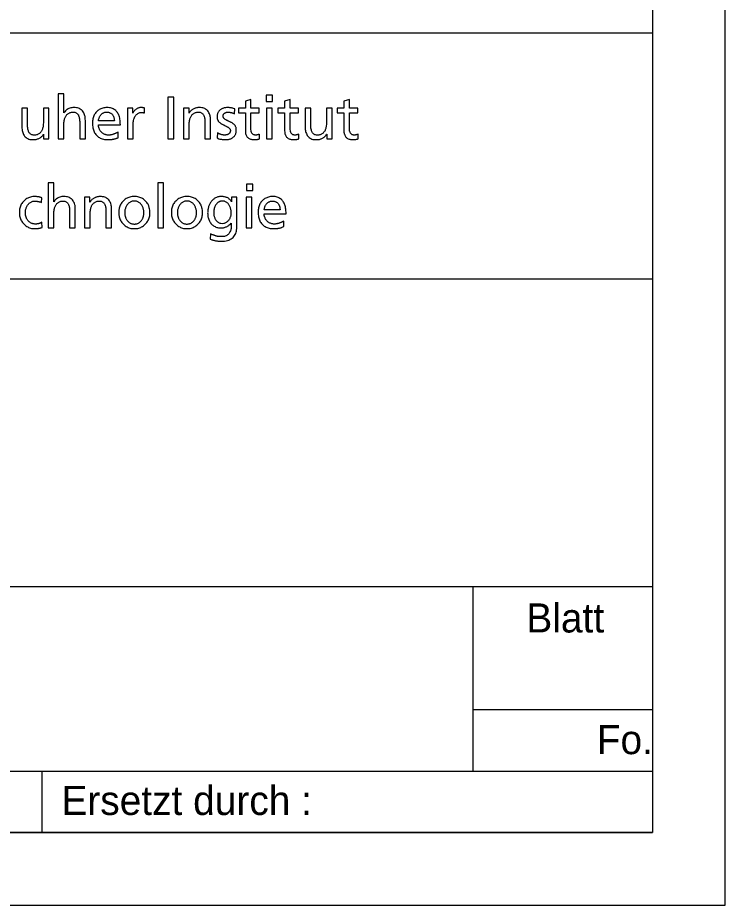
# Model space of a CAD drawing. Extents: x 0 to 148, y 0 to 105.
# Drawn here: x 136.33 to 148.5, y 0 to 15.26 of the extents above; entities that cross this region are included whole.
import ezdxf

# ---------------------------------------------------------------- set-up
doc = ezdxf.new("R2010")
doc.units = 0
doc.layers.add('90_Plankopf', color=7, linetype='Continuous')

msp = doc.modelspace()

# ---------------------------------------------------------------- linework, layer by layer
at = {"layer": '90_Plankopf'}
for p, q in [((147.25, 21.248), (147.25, 1.25)), ((102.78, 14.998), (147.25, 14.998)), ((102.78, 14.998), (147.25, 14.998)), ((147.25, 14.998), (147.25, 1.25)), ((138.514, 13.621), (138.514, 13.708)), ((140.058, 13.61), (140.066, 13.694)), ((137.993, 13.49), (137.721, 13.49)), ((137.721, 13.418), (138.096, 13.418)), ((138.056, 13.198), (138.056, 13.295)), ((139.768, 13.28), (139.763, 13.193)), ((140.49, 13.179), (140.49, 13.261)), ((141.166, 13.179), (141.166, 13.261)), ((142.186, 13.179), (142.186, 13.261)), ((136.738, 12.084), (136.746, 12.165)), ((140.843, 11.96), (140.571, 11.96)), ((140.571, 11.888), (140.946, 11.888)), ((140.906, 11.668), (140.906, 11.765)), ((136.75, 11.656), (136.743, 11.743)), ((139.649, 11.543), (139.639, 11.454)), ((126.25, 10.768), (147.25, 10.768)), ((126.25, 5.48), (147.25, 5.48)), ((144.162, 2.308), (144.162, 5.48)), ((144.162, 3.365), (147.25, 3.365)), ((126.25, 2.308), (147.25, 2.308)), ((136.75, 1.25), (136.75, 2.308)), ((147.25, 1.25), (102.78, 1.25)), ((105.7, 1.25), (147.25, 1.25)), ((105.7, 1.25), (147.25, 1.25))]:
    msp.add_line(p, q, dxfattribs=at)
for points in [[(0, 0), (148.5, 0), (148.5, 105), (0, 105)], [(6.25, 103.75), (147.25, 103.75), (147.25, 1.25), (6.25, 1.25)]]:
    msp.add_lwpolyline(points, close=True, dxfattribs=at)
for points in [[(137.127, 13.627), (137.125, 13.627), (137.125, 13.95), (137.028, 13.95), (137.028, 13.176), (137.125, 13.176), (137.125, 13.42)], [(138.912, 13.176), (139.015, 13.176), (139.015, 13.897), (138.912, 13.897), (138.912, 13.176)], [(140.713, 13.82), (140.713, 13.93), (140.604, 13.93), (140.604, 13.82), (140.713, 13.82)], [(140.343, 13.336), (140.343, 13.624), (140.482, 13.624), (140.482, 13.703), (140.343, 13.703), (140.343, 13.855), (140.246, 13.824), (140.246, 13.703), (140.127, 13.703), (140.127, 13.624), (140.246, 13.624), (140.246, 13.317)], [(141.019, 13.336), (141.019, 13.624), (141.158, 13.624), (141.158, 13.703), (141.019, 13.703), (141.019, 13.855), (140.922, 13.824), (140.922, 13.703), (140.803, 13.703), (140.803, 13.624), (140.922, 13.624), (140.922, 13.317)], [(142.038, 13.336), (142.038, 13.624), (142.178, 13.624), (142.178, 13.703), (142.038, 13.703), (142.038, 13.855), (141.941, 13.824), (141.941, 13.703), (141.823, 13.703), (141.823, 13.624), (141.941, 13.624), (141.941, 13.317)], [(136.501, 13.43), (136.501, 13.703), (136.404, 13.703), (136.404, 13.39)], [(136.773, 13.26), (136.775, 13.26), (136.775, 13.176), (136.869, 13.176), (136.869, 13.703), (136.772, 13.703), (136.772, 13.459)], [(138.313, 13.621), (138.311, 13.621), (138.311, 13.703), (138.22, 13.703), (138.22, 13.176), (138.317, 13.176), (138.317, 13.416)], [(139.279, 13.619), (139.277, 13.619), (139.277, 13.703), (139.183, 13.703), (139.183, 13.176), (139.28, 13.176), (139.28, 13.42)], [(140.61, 13.703), (140.61, 13.176), (140.707, 13.176), (140.707, 13.703), (140.61, 13.703)], [(141.371, 13.43), (141.371, 13.703), (141.274, 13.703), (141.274, 13.39)], [(141.643, 13.26), (141.645, 13.26), (141.645, 13.176), (141.739, 13.176), (141.739, 13.703), (141.642, 13.703), (141.642, 13.459)], [(137.397, 13.449), (137.397, 13.176), (137.494, 13.176), (137.494, 13.489)], [(139.551, 13.449), (139.551, 13.176), (139.648, 13.176), (139.648, 13.489)], [(136.955, 12.097), (136.953, 12.097), (136.953, 12.42), (136.856, 12.42), (136.856, 11.647), (136.953, 11.647), (136.953, 11.89)], [(138.741, 11.647), (138.838, 11.647), (138.838, 12.42), (138.741, 12.42), (138.741, 11.647)], [(140.373, 12.29), (140.373, 12.4), (140.264, 12.4), (140.264, 12.29), (140.373, 12.29)], [(137.576, 12.089), (137.574, 12.089), (137.574, 12.173), (137.48, 12.173), (137.48, 11.647), (137.577, 11.647), (137.577, 11.89)], [(140.099, 11.669), (140.099, 12.173), (140.009, 12.173), (140.009, 12.094), (140.007, 12.094)], [(140.258, 12.173), (140.258, 11.647), (140.355, 11.647), (140.355, 12.173), (140.258, 12.173)], [(137.224, 11.919), (137.224, 11.647), (137.321, 11.647), (137.321, 11.959)], [(137.848, 11.919), (137.848, 11.647), (137.945, 11.647), (137.945, 11.959)], [(140, 11.728), (140.002, 11.728), (140.002, 11.677)]]:
    msp.add_lwpolyline(points, dxfattribs=at)
for points in [[(137.125, 13.42), (137.125, 13.452), (137.128, 13.481), (137.135, 13.508), (137.141, 13.534), (137.151, 13.557), (137.164, 13.576), (137.177, 13.595), (137.194, 13.61), (137.214, 13.621), (137.234, 13.631), (137.258, 13.636), (137.285, 13.637), (137.313, 13.635), (137.335, 13.627), (137.352, 13.613), (137.368, 13.599), (137.38, 13.578), (137.387, 13.551), (137.394, 13.524), (137.397, 13.49), (137.397, 13.449)], [(137.494, 13.489), (137.494, 13.536), (137.487, 13.577), (137.473, 13.61), (137.459, 13.644), (137.437, 13.67), (137.408, 13.688), (137.379, 13.706), (137.342, 13.715), (137.297, 13.715), (137.26, 13.715), (137.227, 13.707), (137.198, 13.692), (137.169, 13.677), (137.145, 13.655), (137.127, 13.627)], [(138.096, 13.418), (138.096, 13.46), (138.092, 13.5), (138.085, 13.536), (138.077, 13.572), (138.064, 13.603), (138.046, 13.63), (138.028, 13.657), (138.004, 13.677), (137.974, 13.692), (137.945, 13.707), (137.908, 13.715), (137.864, 13.715), (137.827, 13.715), (137.793, 13.708), (137.763, 13.695), (137.733, 13.682), (137.707, 13.664), (137.685, 13.64), (137.664, 13.617), (137.647, 13.589), (137.635, 13.556), (137.624, 13.524), (137.618, 13.488), (137.618, 13.449), (137.618, 13.406), (137.623, 13.367), (137.634, 13.332), (137.645, 13.297), (137.661, 13.267), (137.684, 13.242), (137.706, 13.217), (137.734, 13.198), (137.769, 13.184), (137.803, 13.171), (137.843, 13.164), (137.89, 13.164), (137.919, 13.164), (137.943, 13.166), (137.963, 13.17), (137.983, 13.174), (138.001, 13.178), (138.016, 13.183), (138.03, 13.188), (138.044, 13.193), (138.056, 13.198)], [(137.721, 13.49), (137.722, 13.507), (137.726, 13.524), (137.733, 13.542), (137.739, 13.559), (137.747, 13.574), (137.759, 13.589), (137.77, 13.603), (137.784, 13.615), (137.801, 13.623), (137.818, 13.632), (137.838, 13.636), (137.862, 13.637), (137.883, 13.636), (137.902, 13.633), (137.918, 13.625), (137.934, 13.617), (137.948, 13.607), (137.959, 13.594), (137.97, 13.58), (137.979, 13.564), (137.984, 13.547), (137.99, 13.529), (137.993, 13.51), (137.993, 13.49)], [(138.514, 13.708), (138.508, 13.709), (138.501, 13.71), (138.495, 13.712), (138.489, 13.713), (138.482, 13.713), (138.475, 13.714), (138.468, 13.715), (138.46, 13.715), (138.45, 13.715), (138.432, 13.715), (138.413, 13.711), (138.396, 13.703), (138.378, 13.695), (138.362, 13.684), (138.348, 13.67), (138.333, 13.656), (138.322, 13.639), (138.313, 13.621)], [(138.317, 13.416), (138.317, 13.46), (138.323, 13.498), (138.335, 13.53), (138.347, 13.562), (138.363, 13.587), (138.385, 13.604), (138.406, 13.621), (138.432, 13.63), (138.461, 13.63), (138.469, 13.631), (138.478, 13.63), (138.487, 13.629), (138.496, 13.627), (138.505, 13.625), (138.514, 13.621)], [(139.648, 13.489), (139.648, 13.536), (139.641, 13.577), (139.627, 13.61), (139.614, 13.644), (139.592, 13.67), (139.563, 13.688), (139.534, 13.706), (139.497, 13.715), (139.451, 13.715), (139.427, 13.715), (139.403, 13.711), (139.38, 13.704), (139.358, 13.696), (139.338, 13.685), (139.32, 13.67), (139.303, 13.656), (139.289, 13.639), (139.279, 13.619)], [(139.28, 13.42), (139.28, 13.452), (139.283, 13.481), (139.289, 13.508), (139.296, 13.534), (139.305, 13.557), (139.319, 13.576), (139.332, 13.595), (139.348, 13.61), (139.368, 13.621), (139.388, 13.631), (139.412, 13.636), (139.44, 13.637), (139.468, 13.635), (139.49, 13.627), (139.506, 13.613), (139.523, 13.599), (139.534, 13.578), (139.541, 13.551), (139.548, 13.524), (139.551, 13.49), (139.551, 13.449)], [(140.066, 13.694), (140.047, 13.7), (140.028, 13.705), (140.009, 13.709), (139.989, 13.713), (139.968, 13.715), (139.946, 13.715), (139.919, 13.715), (139.895, 13.712), (139.873, 13.705), (139.85, 13.698), (139.831, 13.688), (139.814, 13.675), (139.797, 13.662), (139.784, 13.645), (139.774, 13.625), (139.765, 13.604), (139.76, 13.58), (139.76, 13.553), (139.76, 13.532), (139.764, 13.514), (139.773, 13.498), (139.781, 13.483), (139.791, 13.47), (139.805, 13.459), (139.819, 13.447), (139.833, 13.437), (139.85, 13.429), (139.866, 13.42), (139.882, 13.412), (139.898, 13.404), (139.914, 13.397), (139.929, 13.389), (139.943, 13.38), (139.956, 13.373), (139.967, 13.363), (139.975, 13.353), (139.983, 13.343), (139.988, 13.331), (139.988, 13.318), (139.988, 13.304), (139.985, 13.292), (139.979, 13.282), (139.973, 13.272), (139.965, 13.265), (139.955, 13.259), (139.945, 13.253), (139.935, 13.249), (139.923, 13.246), (139.912, 13.244), (139.9, 13.242), (139.889, 13.242), (139.879, 13.242), (139.867, 13.244), (139.854, 13.247), (139.84, 13.249), (139.825, 13.253), (139.81, 13.259), (139.795, 13.265), (139.781, 13.271), (139.768, 13.28)], [(139.763, 13.193), (139.785, 13.181), (139.809, 13.174), (139.833, 13.17), (139.858, 13.166), (139.882, 13.164), (139.907, 13.164), (139.931, 13.164), (139.954, 13.167), (139.976, 13.174), (139.997, 13.18), (140.017, 13.191), (140.034, 13.204), (140.052, 13.217), (140.065, 13.234), (140.076, 13.255), (140.086, 13.276), (140.091, 13.3), (140.091, 13.328), (140.091, 13.352), (140.087, 13.372), (140.078, 13.389), (140.07, 13.406), (140.059, 13.42), (140.046, 13.431), (140.032, 13.443), (140.017, 13.453), (140.001, 13.461), (139.985, 13.469), (139.969, 13.477), (139.953, 13.484), (139.937, 13.491), (139.922, 13.499), (139.908, 13.507), (139.895, 13.515), (139.884, 13.524), (139.876, 13.534), (139.867, 13.545), (139.863, 13.557), (139.863, 13.573), (139.863, 13.587), (139.868, 13.599), (139.876, 13.609), (139.885, 13.618), (139.896, 13.625), (139.91, 13.63), (139.924, 13.634), (139.939, 13.637), (139.956, 13.637), (139.962, 13.637), (139.969, 13.636), (139.978, 13.634), (139.988, 13.633), (139.997, 13.631), (140.007, 13.628), (140.018, 13.626), (140.027, 13.623), (140.036, 13.62), (140.045, 13.616), (140.052, 13.613), (140.058, 13.61)], [(136.772, 13.459), (136.772, 13.427), (136.769, 13.398), (136.763, 13.371), (136.757, 13.345), (136.747, 13.322), (136.734, 13.303), (136.721, 13.284), (136.704, 13.269), (136.684, 13.258), (136.664, 13.248), (136.64, 13.243), (136.612, 13.242), (136.584, 13.244), (136.562, 13.252), (136.546, 13.266), (136.53, 13.28), (136.518, 13.301), (136.511, 13.328), (136.504, 13.355), (136.501, 13.389), (136.501, 13.43)], [(141.642, 13.459), (141.642, 13.427), (141.639, 13.398), (141.633, 13.371), (141.626, 13.345), (141.617, 13.322), (141.604, 13.303), (141.591, 13.284), (141.574, 13.269), (141.554, 13.258), (141.534, 13.248), (141.51, 13.243), (141.482, 13.242), (141.454, 13.244), (141.432, 13.252), (141.416, 13.266), (141.399, 13.28), (141.388, 13.301), (141.381, 13.328), (141.374, 13.355), (141.371, 13.389), (141.371, 13.43)], [(136.404, 13.39), (136.404, 13.343), (136.411, 13.302), (136.425, 13.269), (136.439, 13.235), (136.46, 13.209), (136.49, 13.191), (136.519, 13.173), (136.556, 13.164), (136.601, 13.164), (136.626, 13.164), (136.649, 13.168), (136.672, 13.176), (136.694, 13.183), (136.715, 13.194), (136.732, 13.209), (136.75, 13.223), (136.764, 13.24), (136.773, 13.26)], [(138.056, 13.295), (138.05, 13.29), (138.041, 13.285), (138.03, 13.279), (138.018, 13.273), (138.005, 13.267), (137.99, 13.261), (137.975, 13.256), (137.96, 13.251), (137.943, 13.248), (137.927, 13.244), (137.91, 13.243), (137.894, 13.242), (137.871, 13.243), (137.849, 13.247), (137.828, 13.255), (137.808, 13.264), (137.789, 13.276), (137.773, 13.291), (137.757, 13.307), (137.744, 13.325), (137.735, 13.347), (137.726, 13.368), (137.721, 13.392), (137.721, 13.418)], [(140.246, 13.317), (140.246, 13.282), (140.253, 13.253), (140.266, 13.23), (140.279, 13.208), (140.297, 13.191), (140.321, 13.18), (140.346, 13.169), (140.374, 13.164), (140.408, 13.164), (140.424, 13.164), (140.438, 13.166), (140.453, 13.169), (140.467, 13.172), (140.479, 13.175), (140.49, 13.179)], [(140.49, 13.261), (140.483, 13.256), (140.474, 13.252), (140.463, 13.248), (140.452, 13.245), (140.439, 13.243), (140.424, 13.242), (140.409, 13.242), (140.396, 13.246), (140.383, 13.253), (140.371, 13.261), (140.361, 13.271), (140.354, 13.285), (140.347, 13.299), (140.343, 13.316), (140.343, 13.336)], [(140.922, 13.317), (140.922, 13.282), (140.929, 13.253), (140.942, 13.23), (140.955, 13.208), (140.973, 13.191), (140.997, 13.18), (141.022, 13.169), (141.05, 13.164), (141.084, 13.164), (141.1, 13.164), (141.114, 13.166), (141.129, 13.169), (141.143, 13.172), (141.155, 13.175), (141.166, 13.179)], [(141.166, 13.261), (141.159, 13.256), (141.15, 13.252), (141.139, 13.248), (141.128, 13.245), (141.115, 13.243), (141.1, 13.242), (141.085, 13.242), (141.072, 13.246), (141.059, 13.253), (141.047, 13.261), (141.037, 13.271), (141.03, 13.285), (141.023, 13.299), (141.019, 13.316), (141.019, 13.336)], [(141.274, 13.39), (141.274, 13.343), (141.281, 13.302), (141.295, 13.269), (141.309, 13.235), (141.33, 13.209), (141.359, 13.191), (141.388, 13.173), (141.426, 13.164), (141.471, 13.164), (141.495, 13.164), (141.519, 13.168), (141.542, 13.176), (141.564, 13.183), (141.584, 13.194), (141.602, 13.209), (141.62, 13.223), (141.633, 13.24), (141.643, 13.26)], [(141.941, 13.317), (141.942, 13.282), (141.948, 13.253), (141.961, 13.23), (141.974, 13.208), (141.993, 13.191), (142.017, 13.18), (142.041, 13.169), (142.07, 13.164), (142.103, 13.164), (142.119, 13.164), (142.134, 13.166), (142.148, 13.169), (142.162, 13.172), (142.175, 13.175), (142.186, 13.179)], [(142.186, 13.261), (142.179, 13.256), (142.17, 13.252), (142.159, 13.248), (142.148, 13.245), (142.135, 13.243), (142.12, 13.242), (142.105, 13.242), (142.091, 13.246), (142.079, 13.253), (142.067, 13.261), (142.057, 13.271), (142.05, 13.285), (142.042, 13.299), (142.039, 13.316), (142.038, 13.336)], [(136.746, 12.165), (136.737, 12.168), (136.725, 12.172), (136.712, 12.175), (136.699, 12.178), (136.685, 12.181), (136.67, 12.182), (136.656, 12.184), (136.642, 12.185), (136.628, 12.185), (136.588, 12.185), (136.551, 12.178), (136.519, 12.165), (136.486, 12.151), (136.458, 12.132), (136.434, 12.107), (136.41, 12.083), (136.392, 12.054), (136.379, 12.02), (136.367, 11.987), (136.36, 11.95), (136.36, 11.91), (136.36, 11.872), (136.367, 11.836), (136.38, 11.803), (136.393, 11.77), (136.411, 11.741), (136.435, 11.716), (136.459, 11.69), (136.487, 11.67), (136.519, 11.656), (136.552, 11.642), (136.589, 11.635), (136.628, 11.634), (136.64, 11.634), (136.653, 11.635), (136.667, 11.636), (136.68, 11.637), (136.694, 11.639), (136.709, 11.642), (136.723, 11.645), (136.737, 11.65), (136.75, 11.656)], [(136.743, 11.743), (136.733, 11.736), (136.722, 11.73), (136.71, 11.726), (136.698, 11.722), (136.686, 11.718), (136.674, 11.716), (136.662, 11.714), (136.65, 11.713), (136.639, 11.713), (136.614, 11.713), (136.592, 11.717), (136.573, 11.724), (136.553, 11.732), (136.537, 11.742), (136.523, 11.755), (136.509, 11.768), (136.498, 11.783), (136.489, 11.8), (136.48, 11.817), (136.474, 11.834), (136.47, 11.853), (136.465, 11.872), (136.463, 11.891), (136.463, 11.91), (136.463, 11.935), (136.467, 11.959), (136.475, 11.983), (136.482, 12.006), (136.493, 12.027), (136.507, 12.046), (136.522, 12.064), (136.539, 12.079), (136.56, 12.09), (136.581, 12.101), (136.605, 12.107), (136.633, 12.107), (136.648, 12.107), (136.665, 12.105), (136.683, 12.101), (136.701, 12.097), (136.719, 12.092), (136.738, 12.084)], [(136.953, 11.89), (136.953, 11.922), (136.956, 11.951), (136.962, 11.978), (136.968, 12.004), (136.978, 12.027), (136.991, 12.046), (137.004, 12.066), (137.021, 12.08), (137.041, 12.091), (137.061, 12.101), (137.085, 12.107), (137.112, 12.107), (137.14, 12.105), (137.163, 12.097), (137.179, 12.083), (137.195, 12.069), (137.207, 12.048), (137.214, 12.021), (137.221, 11.994), (137.224, 11.96), (137.224, 11.919)], [(137.321, 11.959), (137.321, 12.006), (137.314, 12.047), (137.3, 12.081), (137.286, 12.114), (137.264, 12.14), (137.235, 12.158), (137.206, 12.176), (137.169, 12.185), (137.124, 12.185), (137.087, 12.185), (137.054, 12.177), (137.025, 12.162), (136.996, 12.147), (136.972, 12.125), (136.955, 12.097)], [(137.945, 11.959), (137.945, 12.006), (137.938, 12.047), (137.924, 12.081), (137.91, 12.114), (137.889, 12.14), (137.86, 12.158), (137.831, 12.176), (137.793, 12.185), (137.748, 12.185), (137.724, 12.185), (137.7, 12.181), (137.677, 12.174), (137.655, 12.166), (137.635, 12.155), (137.617, 12.141), (137.599, 12.126), (137.586, 12.109), (137.576, 12.089)], [(137.577, 11.89), (137.577, 11.922), (137.58, 11.951), (137.586, 11.978), (137.593, 12.004), (137.602, 12.027), (137.615, 12.046), (137.628, 12.066), (137.645, 12.08), (137.665, 12.091), (137.685, 12.101), (137.709, 12.107), (137.737, 12.107), (137.765, 12.105), (137.787, 12.097), (137.803, 12.083), (137.82, 12.069), (137.831, 12.048), (137.838, 12.021), (137.845, 11.994), (137.848, 11.96), (137.848, 11.919)], [(138.599, 11.973), (138.595, 11.989), (138.591, 12.005), (138.585, 12.02), (138.573, 12.054), (138.555, 12.083), (138.531, 12.107), (138.507, 12.132), (138.479, 12.151), (138.447, 12.165), (138.414, 12.178), (138.377, 12.185), (138.337, 12.185), (138.297, 12.185), (138.26, 12.178), (138.227, 12.165), (138.195, 12.151), (138.166, 12.132), (138.143, 12.107), (138.119, 12.083), (138.101, 12.054), (138.088, 12.02), (138.076, 11.987), (138.069, 11.95), (138.069, 11.91)], [(138.172, 11.91), (138.172, 11.935), (138.176, 11.959), (138.183, 11.983), (138.191, 12.006), (138.202, 12.027), (138.216, 12.046), (138.23, 12.064), (138.247, 12.079), (138.268, 12.09), (138.288, 12.101), (138.311, 12.107), (138.337, 12.107), (138.363, 12.107), (138.386, 12.101), (138.406, 12.09), (138.427, 12.079), (138.444, 12.064), (138.458, 12.046), (138.472, 12.027), (138.483, 12.006), (138.49, 11.983), (138.498, 11.959), (138.501, 11.935), (138.501, 11.91), (138.501, 11.891), (138.499, 11.872), (138.495, 11.853), (138.491, 11.834), (138.485, 11.817), (138.476, 11.8), (138.468, 11.783), (138.457, 11.768), (138.444, 11.755), (138.431, 11.742), (138.416, 11.732), (138.398, 11.724), (138.38, 11.717), (138.36, 11.713), (138.337, 11.713), (138.314, 11.713), (138.294, 11.717), (138.276, 11.724), (138.258, 11.732), (138.243, 11.742), (138.23, 11.755), (138.217, 11.768), (138.206, 11.783), (138.197, 11.8), (138.189, 11.817), (138.183, 11.834), (138.178, 11.853), (138.174, 11.872), (138.172, 11.891), (138.172, 11.91)], [(139.504, 11.973), (139.501, 11.989), (139.496, 12.005), (139.49, 12.02), (139.478, 12.054), (139.46, 12.083), (139.436, 12.107), (139.412, 12.132), (139.384, 12.151), (139.352, 12.165), (139.319, 12.178), (139.282, 12.185), (139.242, 12.185), (139.202, 12.185), (139.165, 12.178), (139.133, 12.165), (139.1, 12.151), (139.072, 12.132), (139.048, 12.107), (139.024, 12.083), (139.006, 12.054), (138.993, 12.02), (138.981, 11.987), (138.974, 11.95), (138.974, 11.91)], [(139.077, 11.91), (139.077, 11.935), (139.081, 11.959), (139.088, 11.983), (139.096, 12.006), (139.107, 12.027), (139.121, 12.046), (139.135, 12.064), (139.152, 12.079), (139.173, 12.09), (139.193, 12.101), (139.216, 12.107), (139.242, 12.107), (139.268, 12.107), (139.291, 12.101), (139.312, 12.09), (139.332, 12.079), (139.349, 12.064), (139.363, 12.046), (139.377, 12.027), (139.388, 12.006), (139.395, 11.983), (139.403, 11.959), (139.406, 11.935), (139.406, 11.91), (139.406, 11.891), (139.404, 11.872), (139.4, 11.853), (139.396, 11.834), (139.39, 11.817), (139.381, 11.8), (139.373, 11.783), (139.362, 11.768), (139.349, 11.755), (139.336, 11.742), (139.321, 11.732), (139.303, 11.724), (139.285, 11.717), (139.265, 11.713), (139.242, 11.713), (139.219, 11.713), (139.199, 11.717), (139.181, 11.724), (139.163, 11.732), (139.148, 11.742), (139.135, 11.755), (139.122, 11.768), (139.111, 11.783), (139.102, 11.8), (139.094, 11.817), (139.088, 11.834), (139.083, 11.853), (139.079, 11.872), (139.077, 11.891), (139.077, 11.91)], [(140.007, 12.094), (139.997, 12.113), (139.985, 12.13), (139.97, 12.143), (139.955, 12.157), (139.936, 12.167), (139.913, 12.174), (139.891, 12.181), (139.864, 12.185), (139.834, 12.185), (139.802, 12.185), (139.773, 12.18), (139.748, 12.169), (139.723, 12.158), (139.701, 12.144), (139.682, 12.126), (139.663, 12.107), (139.648, 12.086), (139.635, 12.062), (139.623, 12.039), (139.614, 12.013), (139.608, 11.987), (139.602, 11.96), (139.598, 11.933), (139.598, 11.906), (139.598, 11.871), (139.603, 11.839), (139.612, 11.808), (139.622, 11.777), (139.636, 11.749), (139.655, 11.725), (139.673, 11.701), (139.696, 11.682), (139.725, 11.668), (139.753, 11.654), (139.786, 11.647), (139.823, 11.647), (139.846, 11.647), (139.868, 11.65), (139.89, 11.656), (139.911, 11.662), (139.932, 11.671), (139.951, 11.683), (139.969, 11.695), (139.986, 11.71), (140, 11.728)], [(139.848, 11.725), (139.825, 11.725), (139.805, 11.73), (139.787, 11.74), (139.769, 11.75), (139.753, 11.764), (139.741, 11.781), (139.728, 11.798), (139.718, 11.818), (139.712, 11.84), (139.705, 11.862), (139.702, 11.886), (139.702, 11.911), (139.702, 11.929), (139.703, 11.947), (139.707, 11.966), (139.711, 11.984), (139.717, 12.002), (139.725, 12.018), (139.733, 12.035), (139.742, 12.05), (139.754, 12.064), (139.766, 12.077), (139.78, 12.087), (139.795, 12.095), (139.811, 12.103), (139.829, 12.107), (139.848, 12.107), (139.874, 12.107), (139.896, 12.101), (139.916, 12.09), (139.935, 12.08), (139.951, 12.065), (139.964, 12.046), (139.976, 12.027), (139.986, 12.006), (139.992, 11.981), (139.999, 11.957), (140.002, 11.931), (140.002, 11.903), (140.002, 11.879), (139.998, 11.856), (139.991, 11.834), (139.983, 11.813), (139.973, 11.794), (139.959, 11.777), (139.945, 11.761), (139.929, 11.748), (139.91, 11.739), (139.892, 11.73), (139.871, 11.725), (139.848, 11.725)], [(140.946, 11.888), (140.946, 11.931), (140.943, 11.97), (140.935, 12.006), (140.927, 12.042), (140.914, 12.073), (140.896, 12.1), (140.878, 12.127), (140.854, 12.148), (140.824, 12.162), (140.795, 12.177), (140.758, 12.185), (140.714, 12.185), (140.677, 12.185), (140.643, 12.178), (140.613, 12.166), (140.583, 12.152), (140.557, 12.134), (140.535, 12.111), (140.514, 12.087), (140.497, 12.059), (140.485, 12.026), (140.474, 11.994), (140.468, 11.958), (140.468, 11.919), (140.468, 11.876), (140.473, 11.837), (140.484, 11.802), (140.495, 11.767), (140.511, 11.737), (140.534, 11.712), (140.556, 11.687), (140.584, 11.668), (140.619, 11.655), (140.653, 11.641), (140.693, 11.634), (140.74, 11.634), (140.769, 11.634), (140.793, 11.636), (140.813, 11.64), (140.834, 11.644), (140.851, 11.648), (140.866, 11.653), (140.88, 11.659), (140.894, 11.664), (140.906, 11.668)], [(140.571, 11.96), (140.573, 11.977), (140.576, 11.995), (140.583, 12.012), (140.589, 12.029), (140.597, 12.045), (140.609, 12.059), (140.62, 12.073), (140.634, 12.085), (140.651, 12.093), (140.668, 12.102), (140.688, 12.107), (140.712, 12.107), (140.733, 12.107), (140.752, 12.103), (140.768, 12.095), (140.784, 12.088), (140.798, 12.077), (140.809, 12.064), (140.82, 12.05), (140.829, 12.035), (140.834, 12.017), (140.84, 11.999), (140.843, 11.981), (140.843, 11.96)], [(138.069, 11.91), (138.069, 11.872), (138.076, 11.836), (138.089, 11.803), (138.102, 11.77), (138.12, 11.741), (138.144, 11.716), (138.167, 11.69), (138.196, 11.67), (138.228, 11.656), (138.261, 11.642), (138.297, 11.635), (138.337, 11.634), (138.377, 11.635), (138.413, 11.642), (138.446, 11.656), (138.478, 11.67), (138.507, 11.69), (138.53, 11.716), (138.554, 11.741), (138.572, 11.77), (138.585, 11.803), (138.598, 11.836), (138.604, 11.872), (138.604, 11.91), (138.604, 11.932), (138.602, 11.953), (138.599, 11.973)], [(138.974, 11.91), (138.974, 11.872), (138.981, 11.836), (138.994, 11.803), (139.007, 11.77), (139.025, 11.741), (139.049, 11.716), (139.072, 11.69), (139.101, 11.67), (139.133, 11.656), (139.166, 11.642), (139.202, 11.635), (139.242, 11.634), (139.282, 11.635), (139.318, 11.642), (139.351, 11.656), (139.383, 11.67), (139.412, 11.69), (139.435, 11.716), (139.459, 11.741), (139.477, 11.77), (139.49, 11.803), (139.503, 11.836), (139.509, 11.872), (139.51, 11.91), (139.509, 11.932), (139.508, 11.953), (139.504, 11.973)], [(140.906, 11.765), (140.9, 11.76), (140.891, 11.755), (140.88, 11.749), (140.868, 11.743), (140.855, 11.737), (140.84, 11.732), (140.825, 11.726), (140.81, 11.722), (140.793, 11.718), (140.777, 11.715), (140.76, 11.713), (140.744, 11.713), (140.721, 11.713), (140.699, 11.717), (140.678, 11.725), (140.658, 11.734), (140.639, 11.746), (140.623, 11.761), (140.607, 11.777), (140.594, 11.795), (140.585, 11.817), (140.576, 11.838), (140.571, 11.862), (140.571, 11.888)], [(139.639, 11.454), (139.667, 11.444), (139.691, 11.437), (139.713, 11.431), (139.734, 11.426), (139.754, 11.423), (139.773, 11.42), (139.791, 11.418), (139.809, 11.418), (139.828, 11.418), (139.89, 11.418), (139.942, 11.428), (139.982, 11.447), (140.022, 11.467), (140.051, 11.495), (140.07, 11.533), (140.09, 11.57), (140.099, 11.616), (140.099, 11.669)], [(140.002, 11.677), (140.002, 11.639), (139.995, 11.607), (139.982, 11.58), (139.969, 11.553), (139.951, 11.533), (139.927, 11.518), (139.902, 11.504), (139.873, 11.496), (139.839, 11.496), (139.821, 11.496), (139.805, 11.497), (139.79, 11.499), (139.774, 11.5), (139.76, 11.503), (139.745, 11.507), (139.73, 11.511), (139.716, 11.516), (139.7, 11.522), (139.684, 11.528), (139.667, 11.535), (139.649, 11.543)]]:
    msp.add_open_spline(points, degree=3, dxfattribs=at)

# ---------------------------------------------------------------- texts
for s, p in [('Blatt', (145.079, 4.69)), ('Fo.', (146.29, 2.598)), ('Ersetzt durch :', (137.082, 1.552))]:
    msp.add_text(s, height=0.5, dxfattribs=at).set_placement(p)

doc.saveas('drawing.dxf')
